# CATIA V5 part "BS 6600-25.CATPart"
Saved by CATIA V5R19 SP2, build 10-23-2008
Part number: BS 6600-25
Bounding box of the stored display mesh (mm): x -59.975 to 59.975, y -59.975 to 59.975, z 0 to 125
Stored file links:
  C:\Users\Bora\Desktop\3D Katı model\BS serisi\BS 6600\BS 6600-25.CATPart
  C:\Program Files\Dassault Systemes\B19\intel_a\reffiles\standard\MetricThickPitch.txt
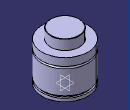
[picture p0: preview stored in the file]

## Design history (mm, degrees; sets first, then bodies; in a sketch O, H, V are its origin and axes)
Body1 (main body)
  Sketch1 on yz-plane, origin (0, 0, 0), H (0, 1, 0), V (0, 0, 1)
    point P1 (60, 79)
    point P2 (60, 74)
    point P3 (60, 79)
    point P7 (37.5, 124)
    point P9 (37.5, 124)
    point P14 (60, 74)
    arc A1 centre (60, 76.5) radius 2.5 from (60, 79) to (60, 74) ccw
    line L1 (60, 79) -> (60, 99)
    line L2 (60, 0) -> (60, 8)
    arc A2 centre (36.5, 124) radius 1 from (37.5, 124) to (36.5, 125) ccw
    line L3 (37.5, 124) -> (37.5, 99)
    line L4 (56, 13) -> (56, 8)
    line L5 (60, 13) -> (60, 74)
    line L6 (36.5, 125) -> (0, 125)
    point P15 (0, 125)
    line L7 (37.5, 99) -> (60, 99)
    line L8 (0, 0) -> (60, 0)
    line L9 (56, 13) -> (60, 13)
    line L10 (56, 8) -> (60, 8)
    coincidence: P15 V, P1 P3, P2 P14, P7 P9
    tangency: L6 A2
    horizontal: L7 H, L8 H, L9 H, L10 H
  Shaft1: profile Sketch1, axis Sketch1.V, angle 360
  Sketch2 on face of Shaft1 from Sketch1.L8, origin (0, 0, 0), H (1, 0, 0), V (0, -1, 0)
    point P1 (40, 0)
    distance P1 V = 40
  Hole1: placed by Sketch2, at (40, 0, 0) direction (0, 0, 1), diameter 8.376, depth 8, threaded "M10", thread diameter 10, thread depth 8, pitch 1.5
  CircPattern1: of Hole1, instances 4, angular step 90, axis from xy-plane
